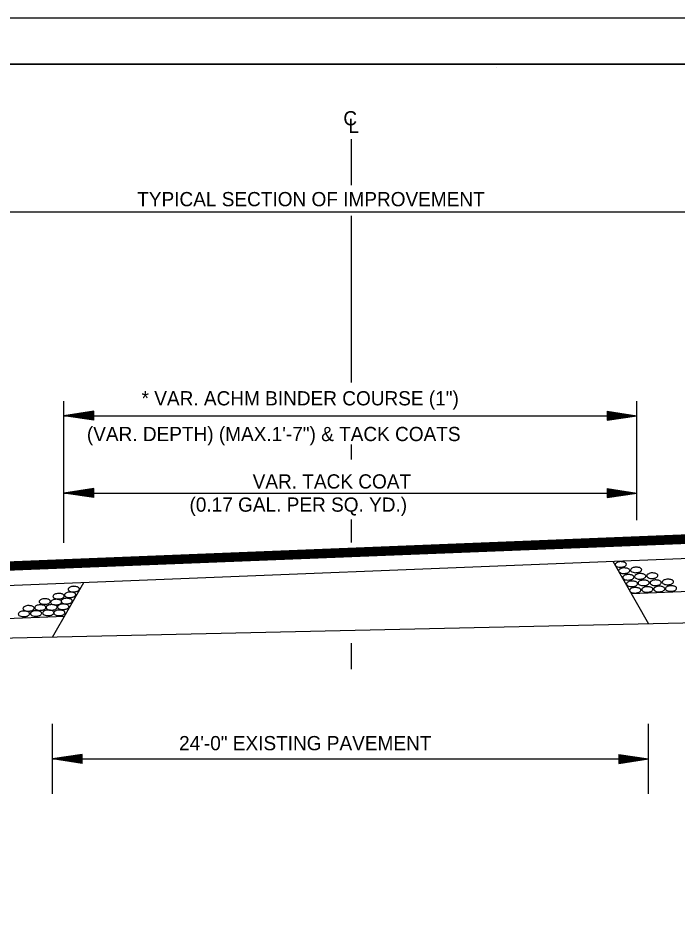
# Model space of a CAD drawing. Extents: x 3575 to 11445, y 9479 to 13278.
# Drawn here: x 4670.2 to 4948.4, y 10707.3 to 11086.2 of the extents above; entities that cross this region are included whole.
import ezdxf

# ---------------------------------------------------------------- set-up
doc = ezdxf.new("R2010")
doc.units = 0
for name, color, linetype in [('_Drafting 1', 7, 'Continuous'), ('R_NoPlot', 7, 'Continuous'), ('STAMP_PE_CRAFTON-SIGNATURE', 7, 'Continuous'), ('STAMP_PRELIMINARY', 7, 'Continuous')]:
    doc.layers.add(name, color=color, linetype=linetype)

msp = doc.modelspace()

# ---------------------------------------------------------------- linework, layer by layer
at = {"layer": '_Drafting 1'}
msp.add_lwpolyline([(4109.53, 11066.7), (4109.53, 10039.4), (5690.43, 10039.4), (5690.43, 11002.7), (5474.93, 11002.7), (5474.93, 11001.26), (5458.74, 11001.26), (5458.74, 11017.3), (5279.13, 11017.3), (5279.13, 11066.7)], close=True, dxfattribs=at)
at = {"layer": 'R_NoPlot'}
msp.add_lwpolyline([(4047.49, 11086.17), (5714.19, 11086.17), (5714.19, 10019.49), (4047.49, 10019.49)], close=True, dxfattribs=at)
at = {"layer": 'STAMP_PE_CRAFTON-SIGNATURE'}
for p, q in [((4810.95, 11015.56), (4810.95, 11035.05)), ((4490.54, 11004.34), (5131.61, 11004.34)), ((4810.95, 10939.75), (4810.95, 11002.7)), ((4810.95, 10932.32), (4810.95, 10939.75)), ((4689.65, 10864.67), (4689.65, 10924.52)), ((4931.48, 10874.26), (4931.48, 10924.52)), ((4702.21, 10920.23), (4689.65, 10918.32)), ((4702.21, 10916.44), (4702.21, 10920.23)), ((4918.91, 10920.23), (4931.48, 10918.32)), ((4918.91, 10920.23), (4918.91, 10916.44)), ((4689.65, 10918.32), (4931.48, 10918.32)), ((4702.21, 10916.44), (4689.65, 10918.32)), ((4702.21, 10919.89), (4691.73, 10918.32)), ((4702.21, 10916.74), (4691.73, 10918.32)), ((4702.21, 10919.62), (4693.89, 10918.32)), ((4702.21, 10917.05), (4693.89, 10918.32)), ((4702.21, 10919.26), (4695.99, 10918.32)), ((4702.21, 10917.38), (4695.99, 10918.32)), ((4702.21, 10918.96), (4698.12, 10918.32)), ((4702.21, 10917.69), (4698.12, 10918.32)), ((4702.21, 10918.62), (4700.23, 10918.32)), ((4702.21, 10918.04), (4700.23, 10918.32)), ((4918.91, 10919.89), (4929.37, 10918.32)), ((4918.91, 10919.62), (4927.2, 10918.32)), ((4918.91, 10919.26), (4925.08, 10918.32)), ((4918.91, 10918.96), (4922.96, 10918.32)), ((4918.91, 10918.62), (4920.89, 10918.32)), ((4918.91, 10916.44), (4931.48, 10918.32)), ((4918.91, 10917.69), (4922.96, 10918.32)), ((4918.91, 10917.05), (4927.2, 10918.32)), ((4918.91, 10916.74), (4929.37, 10918.32)), ((4918.91, 10917.38), (4925.08, 10918.32)), ((4918.91, 10918.04), (4920.89, 10918.32)), ((4810.95, 10899.85), (4810.95, 10906.16)), ((4702.21, 10887.61), (4689.65, 10885.73)), ((4702.21, 10887.32), (4691.73, 10885.73)), ((4702.21, 10886.99), (4693.89, 10885.73)), ((4702.21, 10886.7), (4695.99, 10885.73)), ((4702.21, 10886.33), (4698.12, 10885.73)), ((4702.21, 10886.05), (4700.23, 10885.73)), ((4702.21, 10883.84), (4702.21, 10887.61)), ((4918.91, 10887.61), (4931.48, 10885.73)), ((4918.91, 10887.61), (4918.91, 10883.84)), ((4918.91, 10887.32), (4929.37, 10885.73)), ((4918.91, 10886.99), (4927.2, 10885.73)), ((4918.91, 10886.7), (4925.08, 10885.73)), ((4918.91, 10886.33), (4922.96, 10885.73)), ((4918.91, 10886.05), (4920.89, 10885.73)), ((4689.65, 10885.73), (4931.48, 10885.73)), ((4702.21, 10883.84), (4689.65, 10885.73)), ((4702.21, 10884.18), (4691.73, 10885.73)), ((4702.21, 10884.48), (4693.89, 10885.73)), ((4702.21, 10884.8), (4695.99, 10885.73)), ((4702.21, 10885.12), (4698.12, 10885.73)), ((4702.21, 10885.45), (4700.23, 10885.73)), ((4918.91, 10883.84), (4931.48, 10885.73)), ((4918.91, 10885.12), (4922.96, 10885.73)), ((4918.91, 10884.48), (4927.2, 10885.73)), ((4918.91, 10884.18), (4929.37, 10885.73)), ((4918.91, 10884.8), (4925.08, 10885.73)), ((4918.91, 10885.45), (4920.89, 10885.73)), ((4488.94, 10848.88), (5133.08, 10874.59)), ((4489.79, 10849.32), (5132.33, 10874.95)), ((4490.54, 10849.68), (5131.64, 10875.29)), ((4810.95, 10864.85), (4810.95, 10874.58)), ((4487.26, 10848.04), (5134.52, 10873.86)), ((4488.11, 10848.48), (5133.79, 10874.23)), ((4585.06, 10849.99), (5036.6, 10867.96)), ((4585.34, 10850.37), (5036.34, 10868.35)), ((4585.58, 10850.78), (5036.08, 10868.73)), ((4585.82, 10851.17), (5035.83, 10869.09)), ((4586.09, 10851.57), (5035.54, 10869.51)), ((4580.94, 10843.39), (5040.89, 10861.7)), ((4921.28, 10856.94), (4936.43, 10830.62)), ((4684.78, 10824.96), (4698.07, 10848.05)), ((4929.13, 10843.31), (5050.17, 10848.13)), ((4438.69, 10823.77), (4689.85, 10833.78)), ((4634.33, 10823.83), (4986.73, 10831.75)), ((4810.95, 10811.41), (4810.95, 10822.4)), ((4684.78, 10758.89), (4684.78, 10788.33)), ((4936.43, 10758.89), (4936.43, 10788.33)), ((4697.35, 10775.45), (4684.78, 10773.56)), ((4684.78, 10773.56), (4936.43, 10773.56)), ((4697.35, 10771.68), (4684.78, 10773.56)), ((4697.35, 10775.15), (4686.87, 10773.56)), ((4697.35, 10772), (4686.87, 10773.56)), ((4697.35, 10774.8), (4689.05, 10773.56)), ((4697.35, 10772.31), (4689.05, 10773.56)), ((4697.35, 10774.53), (4691.13, 10773.56)), ((4697.35, 10772.63), (4691.13, 10773.56)), ((4697.35, 10774.16), (4693.28, 10773.56)), ((4697.35, 10772.94), (4693.28, 10773.56)), ((4697.35, 10773.89), (4695.37, 10773.56)), ((4697.35, 10773.27), (4695.37, 10773.56)), ((4697.35, 10771.68), (4697.35, 10775.45)), ((4923.85, 10775.45), (4936.43, 10773.56)), ((4923.85, 10775.45), (4923.85, 10771.68)), ((4923.85, 10775.15), (4934.31, 10773.56)), ((4923.85, 10774.8), (4932.16, 10773.56)), ((4923.85, 10774.53), (4930.07, 10773.56)), ((4923.85, 10774.16), (4927.95, 10773.56)), ((4923.85, 10773.89), (4925.82, 10773.56)), ((4923.85, 10771.68), (4936.43, 10773.56)), ((4923.85, 10772.94), (4927.95, 10773.56)), ((4923.85, 10772.31), (4932.16, 10773.56)), ((4923.85, 10772), (4934.31, 10773.56)), ((4923.85, 10772.63), (4930.07, 10773.56)), ((4923.85, 10773.27), (4925.82, 10773.56))]:
    msp.add_line(p, q, dxfattribs=at)
for points in [[(4924.66, 10854.46), (4923.82, 10854.48), (4922.9, 10854.8), (4922.37, 10855.26), (4922.31, 10855.52), (4922.53, 10856.07), (4922.85, 10856.31), (4923.38, 10856.57), (4924.2, 10856.76), (4924.59, 10856.8), (4925.23, 10856.74), (4925.91, 10856.64), (4926.45, 10856.45), (4926.95, 10856.02), (4927.04, 10855.74), (4926.89, 10855.27), (4926.51, 10854.93), (4926.13, 10854.7), (4925.56, 10854.56), (4925.19, 10854.48), (4924.66, 10854.46)], [(4926.11, 10851.82), (4925.27, 10851.84), (4924.36, 10852.16), (4923.82, 10852.61), (4923.77, 10852.87), (4923.98, 10853.43), (4924.3, 10853.67), (4924.83, 10853.93), (4925.65, 10854.12), (4926.04, 10854.16), (4926.68, 10854.1), (4927.37, 10854), (4927.9, 10853.81), (4928.4, 10853.38), (4928.49, 10853.1), (4928.34, 10852.63), (4927.96, 10852.29), (4927.58, 10852.06), (4927.01, 10851.92), (4926.65, 10851.84), (4926.11, 10851.82)], [(4931.13, 10852.15), (4930.29, 10852.17), (4929.38, 10852.49), (4928.84, 10852.94), (4928.79, 10853.2), (4929, 10853.76), (4929.32, 10854), (4929.85, 10854.26), (4930.67, 10854.45), (4931.06, 10854.49), (4931.7, 10854.43), (4932.39, 10854.33), (4932.92, 10854.14), (4933.42, 10853.71), (4933.51, 10853.43), (4933.36, 10852.96), (4932.98, 10852.62), (4932.6, 10852.39), (4932.03, 10852.25), (4931.67, 10852.17), (4931.13, 10852.15)], [(4932.85, 10849.44), (4932.01, 10849.46), (4931.09, 10849.78), (4930.56, 10850.24), (4930.5, 10850.5), (4930.72, 10851.05), (4931.04, 10851.29), (4931.57, 10851.56), (4932.39, 10851.74), (4932.78, 10851.78), (4933.41, 10851.73), (4934.1, 10851.62), (4934.64, 10851.43), (4935.14, 10851.01), (4935.23, 10850.72), (4935.08, 10850.25), (4934.7, 10849.91), (4934.32, 10849.68), (4933.75, 10849.54), (4933.38, 10849.46), (4932.85, 10849.44)], [(4938, 10849.71), (4937.16, 10849.72), (4936.24, 10850.05), (4935.71, 10850.5), (4935.65, 10850.76), (4935.87, 10851.32), (4936.19, 10851.55), (4936.72, 10851.82), (4937.54, 10852.01), (4937.93, 10852.05), (4938.57, 10851.99), (4939.25, 10851.88), (4939.79, 10851.7), (4940.29, 10851.27), (4940.38, 10850.99), (4940.23, 10850.52), (4939.85, 10850.18), (4939.47, 10849.94), (4938.9, 10849.81), (4938.53, 10849.72), (4938, 10849.71)], [(4927.9, 10849.05), (4927.05, 10849.06), (4926.14, 10849.39), (4925.61, 10849.84), (4925.55, 10850.1), (4925.77, 10850.66), (4926.08, 10850.89), (4926.62, 10851.16), (4927.43, 10851.35), (4927.82, 10851.39), (4928.46, 10851.33), (4929.15, 10851.22), (4929.68, 10851.04), (4930.18, 10850.61), (4930.27, 10850.33), (4930.13, 10849.86), (4929.75, 10849.52), (4929.37, 10849.28), (4928.79, 10849.15), (4928.43, 10849.06), (4927.9, 10849.05)], [(4929.41, 10846.27), (4928.57, 10846.29), (4927.66, 10846.61), (4927.13, 10847.07), (4927.07, 10847.33), (4927.29, 10847.88), (4927.6, 10848.12), (4928.14, 10848.39), (4928.95, 10848.57), (4929.34, 10848.61), (4929.98, 10848.56), (4930.67, 10848.45), (4931.2, 10848.26), (4931.7, 10847.84), (4931.79, 10847.55), (4931.65, 10847.08), (4931.27, 10846.74), (4930.89, 10846.51), (4930.31, 10846.37), (4929.95, 10846.29), (4929.41, 10846.27)], [(4934.3, 10846.67), (4933.46, 10846.69), (4932.55, 10847.01), (4932.01, 10847.46), (4931.96, 10847.72), (4932.17, 10848.28), (4932.49, 10848.51), (4933.02, 10848.78), (4933.84, 10848.97), (4934.23, 10849.01), (4934.87, 10848.95), (4935.56, 10848.85), (4936.09, 10848.66), (4936.59, 10848.23), (4936.68, 10847.95), (4936.53, 10847.48), (4936.15, 10847.14), (4935.77, 10846.91), (4935.2, 10846.77), (4934.84, 10846.69), (4934.3, 10846.67)], [(4939.39, 10846.74), (4938.55, 10846.75), (4937.63, 10847.08), (4937.1, 10847.53), (4937.04, 10847.79), (4937.26, 10848.35), (4937.58, 10848.58), (4938.11, 10848.85), (4938.93, 10849.03), (4939.31, 10849.07), (4939.95, 10849.02), (4940.64, 10848.91), (4941.17, 10848.73), (4941.68, 10848.3), (4941.76, 10848.01), (4941.62, 10847.55), (4941.24, 10847.21), (4940.86, 10846.97), (4940.28, 10846.83), (4939.92, 10846.75), (4939.39, 10846.74)], [(4944.54, 10847.07), (4943.7, 10847.08), (4942.78, 10847.41), (4942.25, 10847.86), (4942.19, 10848.12), (4942.41, 10848.68), (4942.73, 10848.91), (4943.26, 10849.18), (4944.08, 10849.36), (4944.47, 10849.4), (4945.1, 10849.35), (4945.79, 10849.24), (4946.33, 10849.06), (4946.83, 10848.63), (4946.92, 10848.34), (4946.77, 10847.88), (4946.39, 10847.54), (4946.01, 10847.3), (4945.44, 10847.16), (4945.07, 10847.08), (4944.54, 10847.07)], [(4693.76, 10844.04), (4692.92, 10844.06), (4692, 10844.38), (4691.47, 10844.84), (4691.41, 10845.1), (4691.63, 10845.65), (4691.95, 10845.89), (4692.48, 10846.16), (4693.3, 10846.34), (4693.68, 10846.38), (4694.32, 10846.33), (4695.01, 10846.22), (4695.55, 10846.03), (4696.05, 10845.61), (4696.14, 10845.32), (4695.99, 10844.85), (4695.61, 10844.51), (4695.23, 10844.28), (4694.66, 10844.14), (4694.29, 10844.06), (4693.76, 10844.04)], [(4930.74, 10843.57), (4929.89, 10843.58), (4928.98, 10843.91), (4928.45, 10844.36), (4928.39, 10844.62), (4928.61, 10845.18), (4928.92, 10845.41), (4929.46, 10845.68), (4930.27, 10845.86), (4930.66, 10845.9), (4931.3, 10845.85), (4931.99, 10845.74), (4932.52, 10845.56), (4933.02, 10845.13), (4933.11, 10844.84), (4932.97, 10844.38), (4932.59, 10844.04), (4932.21, 10843.8), (4931.63, 10843.66), (4931.27, 10843.58), (4930.74, 10843.57)], [(4935.89, 10843.9), (4935.05, 10843.91), (4934.13, 10844.24), (4933.6, 10844.69), (4933.54, 10844.95), (4933.76, 10845.51), (4934.07, 10845.74), (4934.61, 10846.01), (4935.43, 10846.19), (4935.81, 10846.23), (4936.45, 10846.18), (4937.14, 10846.07), (4937.67, 10845.89), (4938.18, 10845.46), (4938.26, 10845.17), (4938.12, 10844.71), (4937.74, 10844.37), (4937.36, 10844.13), (4936.78, 10843.99), (4936.42, 10843.91), (4935.89, 10843.9)], [(4940.91, 10844.09), (4940.06, 10844.11), (4939.15, 10844.43), (4938.62, 10844.89), (4938.56, 10845.15), (4938.78, 10845.7), (4939.09, 10845.94), (4939.63, 10846.21), (4940.44, 10846.39), (4940.83, 10846.43), (4941.47, 10846.38), (4942.16, 10846.27), (4942.69, 10846.08), (4943.19, 10845.66), (4943.28, 10845.37), (4943.14, 10844.9), (4942.76, 10844.56), (4942.38, 10844.33), (4941.8, 10844.19), (4941.44, 10844.11), (4940.91, 10844.09)], [(4945.86, 10844.29), (4945.02, 10844.31), (4944.1, 10844.63), (4943.57, 10845.09), (4943.51, 10845.34), (4943.73, 10845.9), (4944.05, 10846.14), (4944.58, 10846.4), (4945.4, 10846.59), (4945.79, 10846.63), (4946.43, 10846.57), (4947.11, 10846.47), (4947.65, 10846.28), (4948.15, 10845.85), (4948.24, 10845.57), (4948.09, 10845.1), (4947.71, 10844.76), (4947.33, 10844.53), (4946.76, 10844.39), (4946.39, 10844.31), (4945.86, 10844.29)], [(4681.53, 10838.83), (4680.69, 10838.84), (4679.77, 10839.17), (4679.24, 10839.62), (4679.18, 10839.88), (4679.4, 10840.44), (4679.72, 10840.67), (4680.25, 10840.94), (4681.07, 10841.12), (4681.45, 10841.16), (4682.09, 10841.11), (4682.78, 10841), (4683.31, 10840.82), (4683.82, 10840.39), (4683.91, 10840.11), (4683.76, 10839.64), (4683.38, 10839.3), (4683, 10839.06), (4682.42, 10838.92), (4682.06, 10838.84), (4681.53, 10838.83)], [(4686.32, 10838.57), (4685.48, 10838.59), (4684.56, 10838.91), (4684.03, 10839.36), (4683.97, 10839.62), (4684.19, 10840.18), (4684.5, 10840.42), (4685.04, 10840.68), (4685.86, 10840.87), (4686.24, 10840.91), (4686.88, 10840.85), (4687.57, 10840.75), (4688.1, 10840.56), (4688.61, 10840.13), (4688.69, 10839.85), (4688.55, 10839.38), (4688.17, 10839.04), (4687.79, 10838.81), (4687.21, 10838.67), (4686.85, 10838.59), (4686.32, 10838.57)], [(4687.34, 10841.05), (4686.5, 10841.07), (4685.59, 10841.39), (4685.05, 10841.84), (4685, 10842.1), (4685.22, 10842.66), (4685.53, 10842.9), (4686.07, 10843.16), (4686.88, 10843.35), (4687.27, 10843.39), (4687.91, 10843.33), (4688.6, 10843.23), (4689.13, 10843.04), (4689.63, 10842.61), (4689.72, 10842.33), (4689.58, 10841.86), (4689.2, 10841.52), (4688.82, 10841.29), (4688.24, 10841.15), (4687.88, 10841.07), (4687.34, 10841.05)], [(4690.76, 10839), (4689.92, 10839.01), (4689.01, 10839.34), (4688.48, 10839.79), (4688.42, 10840.05), (4688.64, 10840.61), (4688.95, 10840.84), (4689.49, 10841.11), (4690.3, 10841.3), (4690.69, 10841.34), (4691.33, 10841.28), (4692.02, 10841.17), (4692.55, 10840.99), (4693.05, 10840.56), (4693.14, 10840.28), (4693, 10839.81), (4692.62, 10839.47), (4692.24, 10839.23), (4691.66, 10839.1), (4691.3, 10839.01), (4690.76, 10839)], [(4692.22, 10841.65), (4691.38, 10841.67), (4690.46, 10841.99), (4689.93, 10842.44), (4689.87, 10842.7), (4690.09, 10843.26), (4690.41, 10843.49), (4690.94, 10843.76), (4691.76, 10843.95), (4692.15, 10843.99), (4692.78, 10843.93), (4693.47, 10843.83), (4694.01, 10843.64), (4694.51, 10843.21), (4694.6, 10842.93), (4694.45, 10842.46), (4694.07, 10842.12), (4693.69, 10841.88), (4693.12, 10841.75), (4692.75, 10841.67), (4692.22, 10841.65)], [(4674.68, 10835.92), (4673.84, 10835.94), (4672.93, 10836.26), (4672.4, 10836.71), (4672.34, 10836.97), (4672.56, 10837.53), (4672.87, 10837.76), (4673.41, 10838.03), (4674.22, 10838.22), (4674.61, 10838.26), (4675.25, 10838.2), (4675.94, 10838.1), (4676.47, 10837.91), (4676.97, 10837.48), (4677.06, 10837.2), (4676.92, 10836.73), (4676.54, 10836.39), (4676.16, 10836.15), (4675.58, 10836.02), (4675.22, 10835.94), (4674.68, 10835.92)], [(4679.65, 10836.26), (4678.8, 10836.28), (4677.89, 10836.6), (4677.36, 10837.05), (4677.3, 10837.31), (4677.52, 10837.87), (4677.83, 10838.11), (4678.37, 10838.37), (4679.18, 10838.56), (4679.57, 10838.6), (4680.21, 10838.54), (4680.9, 10838.44), (4681.43, 10838.25), (4681.93, 10837.82), (4682.02, 10837.54), (4681.88, 10837.07), (4681.5, 10836.73), (4681.12, 10836.5), (4680.54, 10836.36), (4680.18, 10836.28), (4679.65, 10836.26)], [(4684.44, 10836.35), (4683.59, 10836.36), (4682.68, 10836.69), (4682.15, 10837.14), (4682.09, 10837.4), (4682.31, 10837.96), (4682.62, 10838.19), (4683.16, 10838.46), (4683.97, 10838.64), (4684.36, 10838.68), (4685, 10838.63), (4685.69, 10838.52), (4686.22, 10838.34), (4686.72, 10837.91), (4686.81, 10837.63), (4686.67, 10837.16), (4686.29, 10836.82), (4685.91, 10836.58), (4685.33, 10836.44), (4684.97, 10836.36), (4684.44, 10836.35)], [(4689.31, 10836.6), (4688.47, 10836.62), (4687.55, 10836.94), (4687.02, 10837.4), (4686.96, 10837.66), (4687.18, 10838.21), (4687.5, 10838.45), (4688.03, 10838.71), (4688.85, 10838.9), (4689.24, 10838.94), (4689.88, 10838.88), (4690.56, 10838.78), (4691.1, 10838.59), (4691.6, 10838.16), (4691.69, 10837.88), (4691.54, 10837.41), (4691.16, 10837.07), (4690.78, 10836.84), (4690.21, 10836.7), (4689.84, 10836.62), (4689.31, 10836.6)], [(4672.72, 10833.61), (4671.88, 10833.63), (4670.96, 10833.95), (4670.43, 10834.4), (4670.37, 10834.66), (4670.59, 10835.22), (4670.91, 10835.45), (4671.44, 10835.72), (4672.26, 10835.91), (4672.65, 10835.95), (4673.28, 10835.89), (4673.97, 10835.79), (4674.51, 10835.6), (4675.01, 10835.17), (4675.1, 10834.89), (4674.95, 10834.42), (4674.57, 10834.08), (4674.19, 10833.84), (4673.62, 10833.71), (4673.25, 10833.63), (4672.72, 10833.61)], [(4677.85, 10833.78), (4677.01, 10833.8), (4676.09, 10834.12), (4675.56, 10834.57), (4675.5, 10834.83), (4675.72, 10835.39), (4676.04, 10835.63), (4676.57, 10835.89), (4677.39, 10836.08), (4677.78, 10836.12), (4678.42, 10836.06), (4679.1, 10835.96), (4679.64, 10835.77), (4680.14, 10835.34), (4680.23, 10835.06), (4680.08, 10834.59), (4679.7, 10834.25), (4679.32, 10834.02), (4678.75, 10833.88), (4678.38, 10833.8), (4677.85, 10833.78)], [(4682.98, 10834.04), (4682.14, 10834.05), (4681.23, 10834.38), (4680.69, 10834.83), (4680.64, 10835.09), (4680.85, 10835.65), (4681.17, 10835.88), (4681.7, 10836.15), (4682.52, 10836.34), (4682.91, 10836.38), (4683.55, 10836.32), (4684.23, 10836.21), (4684.77, 10836.03), (4685.27, 10835.6), (4685.36, 10835.32), (4685.21, 10834.85), (4684.83, 10834.51), (4684.45, 10834.27), (4683.88, 10834.13), (4683.51, 10834.05), (4682.98, 10834.04)], [(4687.69, 10834.04), (4686.84, 10834.05), (4685.93, 10834.38), (4685.4, 10834.83), (4685.34, 10835.09), (4685.56, 10835.65), (4685.87, 10835.88), (4686.41, 10836.15), (4687.22, 10836.34), (4687.61, 10836.38), (4688.25, 10836.32), (4688.94, 10836.21), (4689.47, 10836.03), (4689.97, 10835.6), (4690.06, 10835.32), (4689.92, 10834.85), (4689.54, 10834.51), (4689.16, 10834.27), (4688.58, 10834.13), (4688.22, 10834.05), (4687.69, 10834.04)]]:
    msp.add_spline(points, degree=3, dxfattribs=at)
at = {"layer": 'STAMP_PRELIMINARY'}
for p, q in [((4109.53, 11066.7), (5690.43, 11066.7)), ((4872.13, 11065.4), (4872.13, 11065.4)), ((4872.13, 11065.4), (4872.13, 11065.4))]:
    msp.add_line(p, q, dxfattribs=at)

# ---------------------------------------------------------------- texts
at = {"layer": 'STAMP_PE_CRAFTON-SIGNATURE'}
for s, p in [('C', (4807.57, 11040.86)), ('L', (4809.72, 11037.7)), ('TYPICAL SECTION OF IMPROVEMENT', (4720.56, 11006.74)), ('* VAR. ACHM BINDER COURSE (1")', (4722.4, 10922.72)), ('(VAR. DEPTH) (MAX.1\'-7") & TACK COATS', (4699.31, 10907.65)), ('VAR. TACK COAT', (4769.29, 10887.64)), ('(0.17 GAL. PER SQ. YD.)', (4742.62, 10877.86)), ('24\'-0" EXISTING PAVEMENT', (4738.24, 10777.22))]:
    msp.add_text(s, height=6, dxfattribs=at).set_placement(p)

doc.saveas('drawing.dxf')
